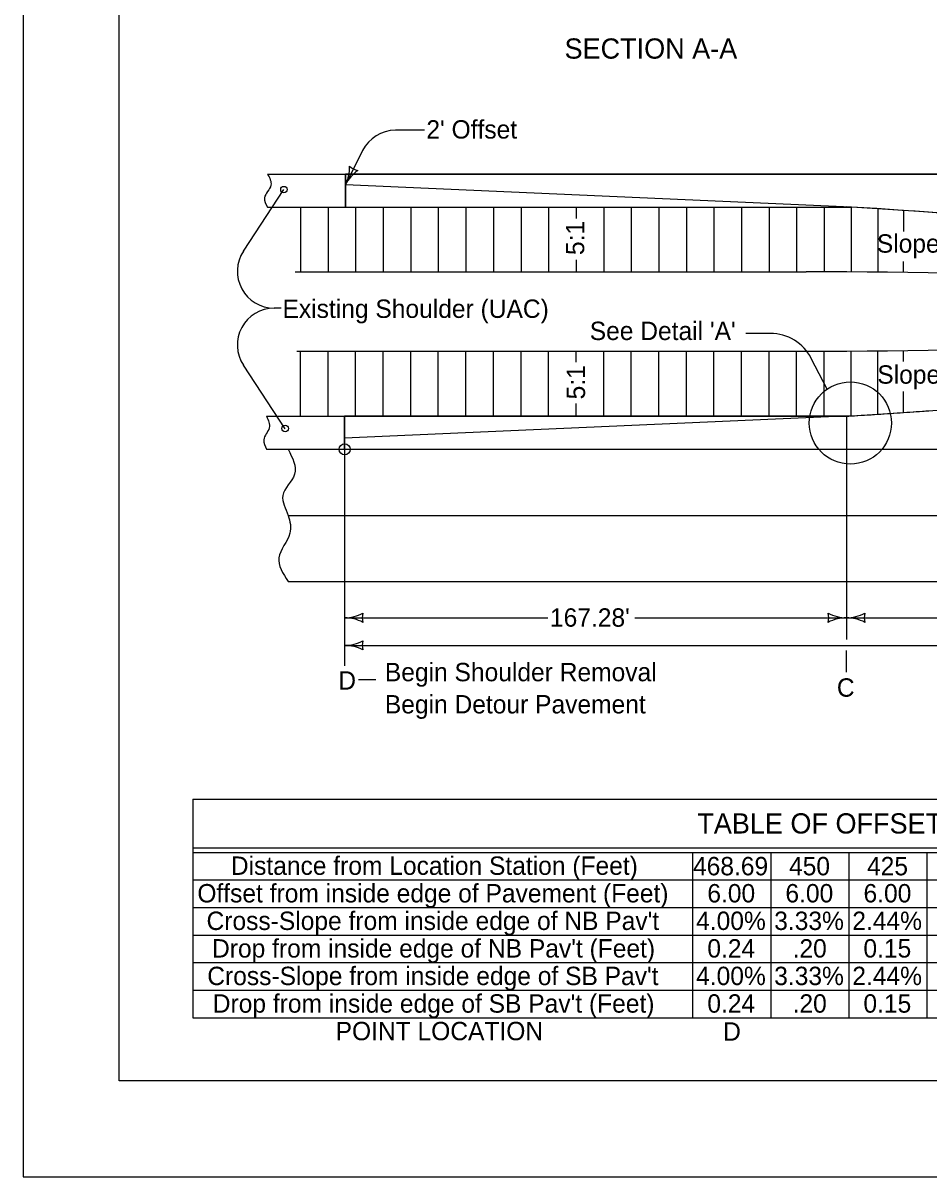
# Model space of a CAD drawing. Extents: x 10028 to 81668, y 3581 to 11018.
# Drawn here: x 13628 to 14614, y 3581 to 4837 of the extents above; entities that cross this region are included whole.
import ezdxf

# ---------------------------------------------------------------- set-up
doc = ezdxf.new("R2010")
doc.units = 0
for name, color, linetype in [('dsnCellElements', 7, 'Continuous'), ('dsnCellsNorthArrow', 7, 'Continuous'), ('DsnShtRevisedText', 7, 'Continuous'), ('dsnStdShading', 7, 'Continuous'), ('dsnTextFinalPlan', 7, 'Continuous'), ('dsnTextTabulation', 7, 'Continuous'), ('Level 11', 7, 'Continuous'), ('Level 6', 7, 'Continuous'), ('Level 7', 7, 'Continuous'), ('Level 9', 7, 'Continuous'), ('SheetAddendum', 7, 'Continuous'), ('ShtPlotIdentification', 7, 'Continuous')]:
    doc.layers.add(name, color=color, linetype=linetype)

msp = doc.modelspace()

# ---------------------------------------------------------------- linework, layer by layer
at = {"layer": 'dsnCellsNorthArrow'}
for p, q in [((14529.4, 4636.7), (13978.9, 4661)), ((14529.4, 4409.4), (13978, 4385.1)), ((13916.5, 4301.1), (14824.8, 4301.1))]:
    msp.add_line(p, q, dxfattribs=at)
at = {"layer": 'DsnShtRevisedText'}
msp.add_lwpolyline([(13732.5, 5695.6), (16867.5, 5695.6), (16867.5, 3685.6), (13732.5, 3685.6)], close=True, dxfattribs=at)
at = {"layer": 'dsnStdShading'}
for p, q in [((15516.2, 4672.7), (13978.9, 4672.7)), ((13978.9, 4672.7), (13978.9, 4636.7)), ((14333.5, 4409.1), (13978, 4409.1)), ((13978, 4409.1), (13978, 4373.1)), ((14524.3, 4409.1), (14480.2, 4409.1)), ((14529.4, 4409.4), (14529.4, 4409.4)), ((14558.2, 4411.2), (14558.2, 4411.2)), ((14586.4, 4413.1), (14586.4, 4413.1)), ((13978, 4373.1), (15516.2, 4373.1))]:
    msp.add_line(p, q, dxfattribs=at)
for points in [[(13978.9, 4636.7), (14410, 4636.7), (14440, 4636.7), (14470, 4636.7), (14500, 4636.7), (14529.4, 4636.7)], [(14529.4, 4636.7), (14529.4, 4636.7)], [(14480.2, 4409.1), (14470, 4409.1), (14333.5, 4409.1)], [(14333.5, 4409.1), (14333.5, 4409.1)], [(14480.2, 4409.1), (14480.2, 4409.1)], [(14529.4, 4409.4), (14529.4, 4409.4)], [(14558.2, 4411.2), (14558.2, 4411.2)], [(14586.4, 4413.1), (14586.4, 4413.1)]]:
    msp.add_lwpolyline(points, dxfattribs=at)
for centre, radius, start, end in [((14003, -3944.1), 8597, 83.51664, 86.48991), ((14003.1, 12988.9), 8595.6, 273.47608, 273.51017), ((14003.1, 12988.9), 8595.6, 273.51017, 273.70252), ((14003.1, 12988.9), 8595.6, 273.70252, 273.89091), ((14003.1, 12988.9), 8595.6, 273.89091, 274.07532)]:
    msp.add_arc(centre, radius, start, end, dxfattribs=at)
at = {"layer": 'dsnTextFinalPlan'}
for p, q in [((14064.9, 4720.3), (14033.3, 4720.3)), ((13997.5, 4698.2), (13978.9, 4661)), ((13867.9, 4588.7), (13911.9, 4655.8)), ((13908.8, 4526.7), (13901.2, 4526.7)), ((14441.4, 4499.3), (14414.8, 4499.3)), ((14503.1, 4438.4), (14485.9, 4472)), ((13913.3, 4395.3), (13867.8, 4464.8)), ((14524.3, 4409.1), (14524.3, 4166.2)), ((13978, 4373.1), (13978, 4137.5)), ((13978, 4189.7), (14199.2, 4189.7)), ((14293.8, 4189.7), (14524.3, 4189.7)), ((14524.3, 4189.7), (14939.4, 4189.7)), ((13978, 4159.7), (14887.3, 4159.7)), ((14524.3, 4130.6), (14524.3, 4154.1)), ((13993, 4122.5), (14011.9, 4122.5))]:
    msp.add_line(p, q, dxfattribs=at)
for centre, radius in [((13911.9, 4655.8), 3.5), ((14528.5, 4401.7), 44.7), ((13913.3, 4395.7), 3.5), ((13978, 4373.1), 6)]:
    msp.add_circle(centre, radius, dxfattribs=at)
for centre, radius, start, end in [((14033.3, 4680.3), 40, 90, 153.446), ((13940.9, 4680), 42.5, 333.446, 1.5185), ((14017, 4642), 42.5, 125.3735, 153.446), ((13994.9, 4692.9), 16.4, 225.7126, 261.1793), ((13901.3, 4566.7), 40, 146.6736, 270), ((13901.2, 4486.7), 40, 90, 213.2786), ((14441.4, 4449.3), 50, 26.9846, 90), ((13978, 4232.2), 42.5, 270, 298.0725), ((13978, 4147.2), 42.5, 61.9275, 90), ((14013.6, 4189.7), 16.4, 162.2666, 197.7334), ((14488.6, 4189.7), 16.4, 342.2666, 17.7333), ((14524.3, 4232.2), 42.5, 241.9275, 270), ((14524.3, 4147.2), 42.5, 90, 118.0725), ((14524.3, 4232.2), 42.5, 270, 298.0725), ((14524.3, 4147.2), 42.5, 61.9275, 90), ((14559.9, 4189.7), 16.4, 162.2666, 197.7334), ((13978, 4202.2), 42.5, 270, 298.0725), ((13978, 4117.2), 42.5, 61.9275, 90), ((14013.6, 4159.7), 16.4, 162.2666, 197.7334)]:
    msp.add_arc(centre, radius, start, end, dxfattribs=at)
at = {"layer": 'dsnTextTabulation'}
for p, q in [((13812.7, 3939.4), (16056.8, 3939.4)), ((13812.7, 3934.4), (16056.8, 3934.4)), ((14356.8, 3934.4), (14356.8, 3754.4)), ((14441.8, 3934.4), (14441.8, 3754.4)), ((14526.8, 3934.4), (14526.8, 3754.4)), ((14611.8, 3934.4), (14611.8, 3754.4))]:
    msp.add_line(p, q, dxfattribs=at)
at = {"layer": 'Level 11'}
for p, q in [((13812.7, 3992.4), (16056.8, 3992.4)), ((13812.7, 3992.4), (13812.7, 3754.4)), ((13812.7, 3754.4), (16056.8, 3754.4))]:
    msp.add_line(p, q, dxfattribs=at)
at = {"layer": 'Level 9'}
for p, q in [((13812.7, 3904.4), (16056.8, 3904.4)), ((13812.7, 3874.4), (16056.8, 3874.4)), ((13812.7, 3844.4), (16056.8, 3844.4)), ((13812.7, 3814.4), (16056.8, 3814.4)), ((13812.7, 3784.4), (16056.8, 3784.4))]:
    msp.add_line(p, q, dxfattribs=at)
at = {"layer": 'SheetAddendum'}
for p, q in [((13894.1, 4672.7), (13978.9, 4672.7)), ((13978.9, 4636.7), (13978.9, 4672.7)), ((13978.9, 4636.7), (13978.9, 4672.7)), ((13978.9, 4672.7), (15516.2, 4672.7)), ((13894.1, 4636.7), (13978.9, 4636.7)), ((13930, 4636.4), (13930, 4566.3)), ((13960, 4636.4), (13960, 4566.3)), ((13978.9, 4636.7), (14529.4, 4636.7)), ((13990, 4636.4), (13990, 4566.3)), ((14020, 4636.4), (14020, 4566.3)), ((14050, 4636.4), (14050, 4566.3)), ((14080, 4636.4), (14080, 4566.3)), ((14110, 4636.4), (14110, 4566.3)), ((14140, 4636.4), (14140, 4566.3)), ((14170, 4636.4), (14170, 4566.3)), ((14200, 4636.4), (14200, 4566.3)), ((14230, 4636.4), (14230, 4624.3)), ((14260, 4636.4), (14260, 4566.3)), ((14290, 4636.4), (14290, 4566.3)), ((14320, 4636.4), (14320, 4566.3)), ((14350, 4636.4), (14350, 4566.3)), ((14380, 4636.4), (14380, 4566.3)), ((14410, 4637.1), (14410, 4566.3)), ((14440, 4637.1), (14440, 4566.3)), ((14470, 4637.1), (14470, 4566.3)), ((14500, 4637.1), (14500, 4566.3)), ((14529.4, 4636.7), (14529.4, 4566.3)), ((14558.2, 4634.9), (14558.2, 4566.3)), ((14586.4, 4633.1), (14586.4, 4610.2)), ((14230, 4579.4), (14230, 4566.3)), ((14586.4, 4565.5), (14586.4, 4577.6)), ((13924.2, 4566.3), (14480.2, 4566.3)), ((13926, 4479.9), (14480.2, 4479.9)), ((13930, 4409.3), (13930, 4479.9)), ((13960, 4409.3), (13960, 4479.9)), ((13990, 4409.3), (13990, 4479.9)), ((14020, 4409.3), (14020, 4479.9)), ((14050, 4409.3), (14050, 4479.9)), ((14080, 4409.3), (14080, 4479.9)), ((14110, 4409.3), (14110, 4479.9)), ((14140, 4409.3), (14140, 4479.9)), ((14170, 4409.3), (14170, 4479.9)), ((14200, 4409.3), (14200, 4479.9)), ((14230, 4468.1), (14230, 4479.9)), ((14260, 4409.3), (14260, 4479.9)), ((14290, 4409.3), (14290, 4479.9)), ((14320, 4409.3), (14320, 4479.9)), ((14350, 4409.3), (14350, 4479.9)), ((14380, 4409.3), (14380, 4479.9)), ((14410, 4409.3), (14410, 4479.9)), ((14440, 4409.3), (14440, 4479.9)), ((14470, 4408.5), (14470, 4479.9)), ((14500, 4410.1), (14500, 4479.9)), ((14529.4, 4409.4), (14529.4, 4479.9)), ((14558.2, 4411.2), (14558.2, 4479.9)), ((14586.4, 4468.6), (14586.4, 4480.6)), ((14586.4, 4413.1), (14586.4, 4435.9)), ((14230, 4409.3), (14230, 4423.1)), ((13893.1, 4409.1), (13978, 4409.1)), ((13978, 4373.1), (13978, 4409.1)), ((13978, 4409.1), (14524.3, 4409.1)), ((14333.5, 4409.1), (14480.2, 4409.1)), ((13893.1, 4373.1), (13978, 4373.1)), ((13978, 4373.1), (15516.2, 4373.1)), ((13916.5, 4229.1), (15755.5, 4229.1))]:
    msp.add_line(p, q, dxfattribs=at)
for centre, radius, start, end in [((14003, -3944.1), 8597, 80.50385, 86.52493), ((14480.2, -3067), 7633.3, 84.67428, 90), ((14480.2, 12113.1), 7633.3, 270, 275.32661), ((14003.1, 12988.9), 8595.6, 273.47608, 279.49716)]:
    msp.add_arc(centre, radius, start, end, dxfattribs=at)
for points in [[(13894.1, 4672.7), (13897.8, 4660.5), (13890.9, 4646.8), (13894.1, 4636.7)], [(13893.1, 4409.1), (13895.9, 4396.4), (13889.9, 4383.5), (13893.1, 4373.1)], [(13916.5, 4373.1), (13923.5, 4345.9), (13910.7, 4322.7), (13916.5, 4301.1), (13918.4, 4281.7), (13906.4, 4255.1), (13916.5, 4229.1)]]:
    msp.add_spline(points, degree=3, dxfattribs=at)
at = {"layer": 'ShtPlotIdentification'}
msp.add_lwpolyline([(13628, 3581.1), (16972, 3581.1), (16972, 6165.1), (13628, 6165.1)], close=True, dxfattribs=at)

# ---------------------------------------------------------------- texts
at = {"layer": 'dsnCellElements'}
for s, height, p in [('TABLE OF OFFSETS AND DROPS (PAVED SHOULDERS) NORTH CROSSOVER', 22, (14361.9, 3954.9)), ('3.33%', 20, (14445.6, 3849.9)), ('2.44%', 20, (14530.6, 3849.9)), ('.20', 20, (14465.6, 3819.9)), ('0.15', 20, (14542.7, 3819.9)), ('3.33%', 20, (14445.6, 3789.9)), ('2.44%', 20, (14530.6, 3789.9)), ('.20', 20, (14465.6, 3759.9)), ('0.15', 20, (14542.7, 3759.9))]:
    msp.add_text(s, height=height, dxfattribs=at).set_placement(p)
at = {"layer": 'Level 6'}
for s, p in [("2' Offset", (14067, 4711.3)), ('Slope Varies', (14557.3, 4587.1)), ('Existing Shoulder (UAC)', (13910.4, 4516.1)), ("See Detail 'A'", (14244.8, 4492)), ('Slope Varies', (14557.8, 4444.5)), ("167.28'", (14201.5, 4180)), ('Begin Shoulder Removal', (14021.8, 4120.6)), ('D', (13971.1, 4111.5)), ('C', (14513.8, 4103.8)), ('Begin Detour Pavement', (14021.8, 4085.6)), ('Distance from Location Station (Feet)', (13854.2, 3909.9)), ('468.69', (14357.2, 3909.4)), ('450', (14461.7, 3909.4)), ('425', (14546.6, 3909.4)), ('Offset from inside edge of Pavement (Feet)', (13817.7, 3879.9)), ('6.00', (14372.8, 3879.9)), ('6.00', (14457.8, 3879.9)), ('6.00', (14542.8, 3879.9)), ("Cross-Slope from inside edge of NB Pav't", (13827.7, 3849.9)), ('4.00%', (14360.6, 3849.9)), ("Drop from inside edge of NB Pav't (Feet)", (13833.7, 3819.9)), ('0.24', (14372.8, 3819.9)), ("Cross-Slope from inside edge of SB Pav't", (13828.5, 3789.9)), ('4.00%', (14360.6, 3789.9)), ("Drop from inside edge of SB Pav't (Feet)", (13834.5, 3759.9)), ('0.24', (14372.8, 3759.9)), ('POINT LOCATION', (13968.2, 3729.9)), ('D', (14390, 3729.4))]:
    msp.add_text(s, height=20, dxfattribs=at).set_placement(p)
for p in [(14238.8, 4584.5), (14239.7, 4427.4)]:
    msp.add_text('5:1', height=20, rotation=90, dxfattribs=at).set_placement(p)
at = {"layer": 'Level 7'}
msp.add_text('SECTION A-A', height=22, dxfattribs=at).set_placement((14217.4, 4798.3))

doc.saveas('drawing.dxf')
